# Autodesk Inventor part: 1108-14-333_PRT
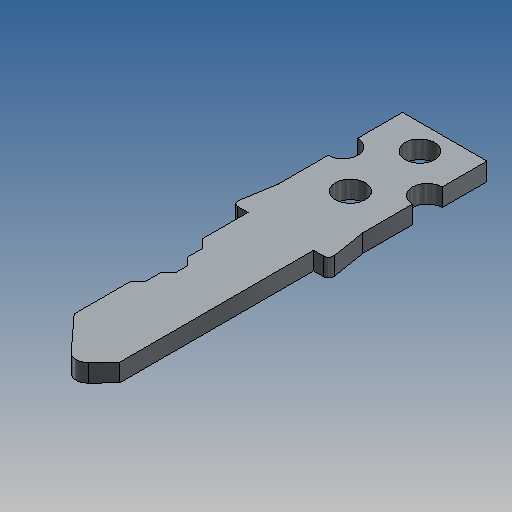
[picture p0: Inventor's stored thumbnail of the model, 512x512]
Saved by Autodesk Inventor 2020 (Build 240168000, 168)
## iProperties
Created: 2007-03
Part Number: 1108-14-333_PRT
Document SubType Name: Modeling
Designer: Andy Moles
Density: 1 g/cm^3
Mass: 0.443583 g
Surface Area: 6.97725 cm^2
Volume: 0.443583 cm^3
Material: Generic
Appearance: TranslatedColorStyle
Author: Andy Moles
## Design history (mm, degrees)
feature "Base1"
body "Solid1"
